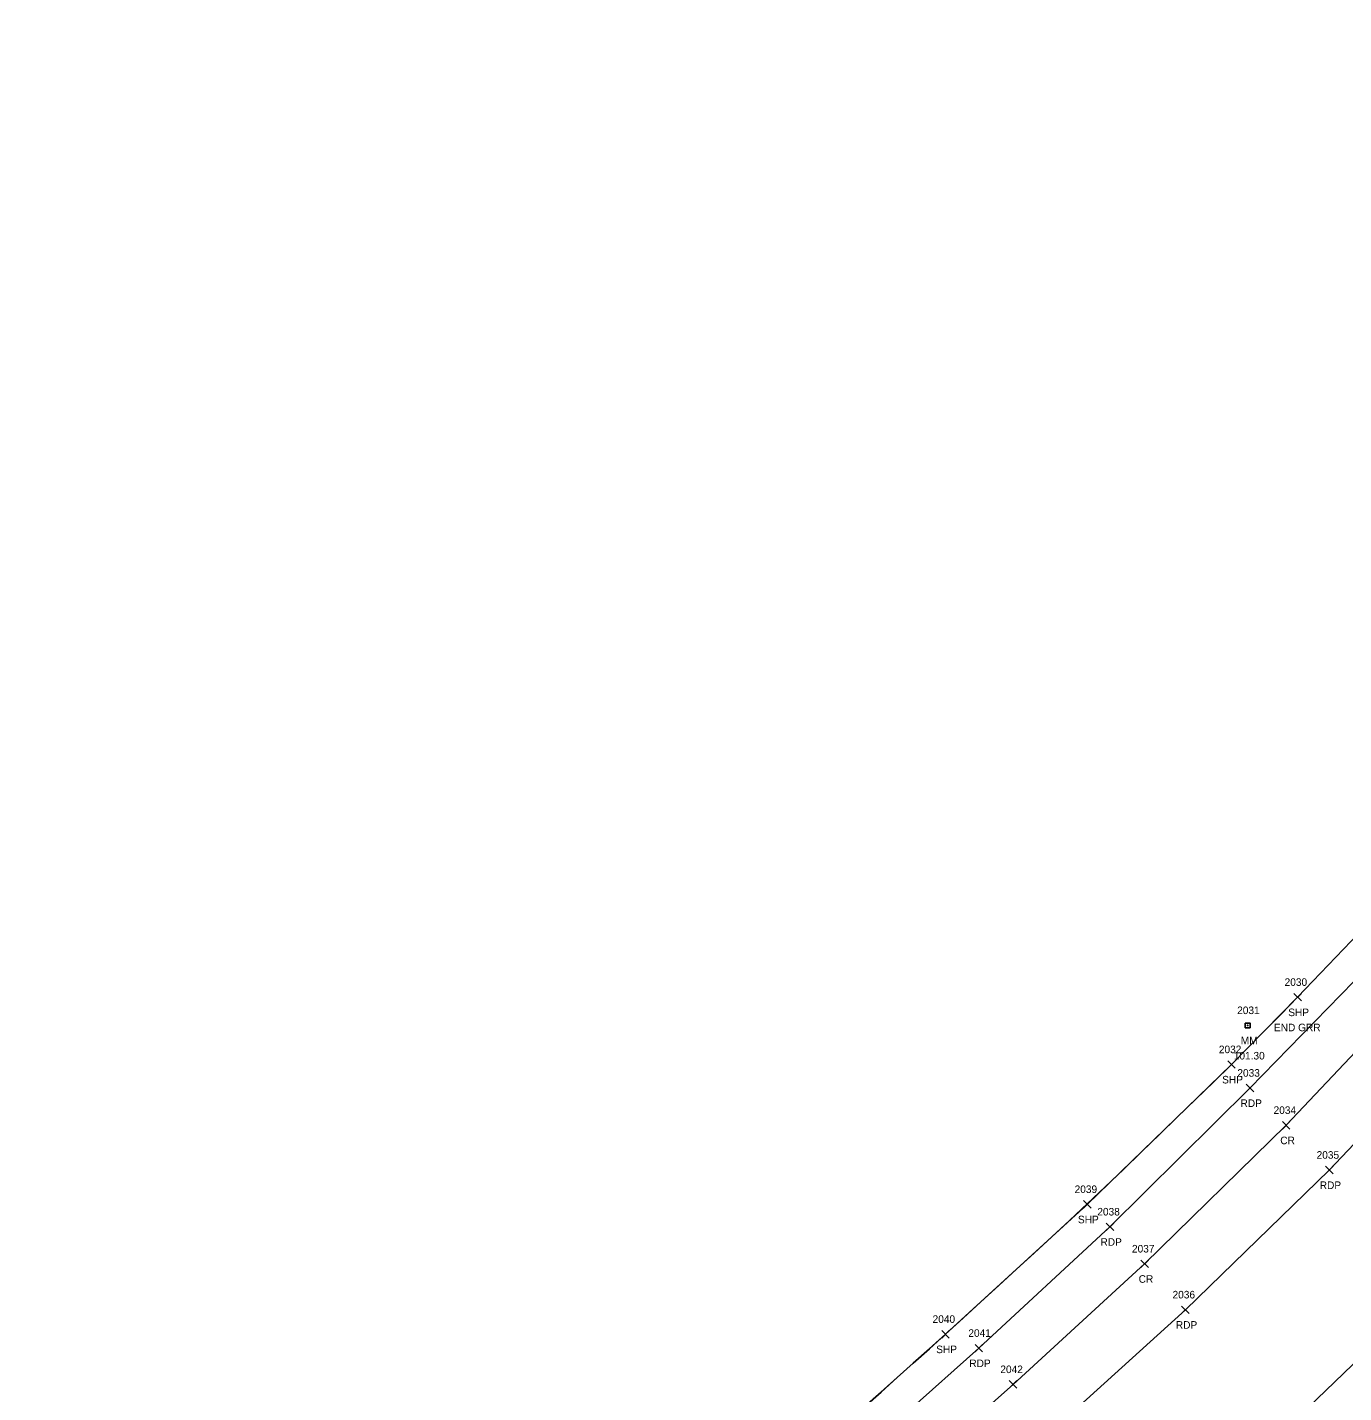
# Model space of a CAD drawing. Extents: x 1472022 to 1479249, y 777216 to 786527.
# Drawn here: x 1472693.8 to 1473041.7, y 778071.1 to 778431.9 of the extents above; entities that cross this region are included whole.
import ezdxf

# ---------------------------------------------------------------- set-up
doc = ezdxf.new("R2010")
doc.units = 0
for name, color, linetype in [('LSOGP', 7, 'Continuous'), ('P_A', 7, 'Continuous'), ('P_C', 7, 'Continuous'), ('P_I', 7, 'Continuous'), ('P_TIC', 7, 'Continuous'), ('PET', 7, 'Continuous'), ('PRC', 7, 'Continuous'), ('PSP', 7, 'Continuous'), ('S_A', 7, 'Continuous'), ('S_C', 7, 'Continuous'), ('S_I', 7, 'Continuous'), ('SRM', 7, 'Continuous')]:
    doc.layers.add(name, color=color, linetype=linetype)

msp = doc.modelspace()

# ---------------------------------------------------------------- linework, layer by layer
at = {"layer": 'LSOGP'}
msp.add_lwpolyline([(1473045.72, 778192.54), (1473041.66, 778188.31), (1473037.61, 778184.07), (1473033.55, 778179.83), (1473029.49, 778175.6), (1473025.13, 778171.15), (1473020.76, 778166.71), (1473016.39, 778162.26), (1473012.03, 778157.81), (1473007.26, 778153.19), (1473002.5, 778148.57), (1472997.74, 778143.95), (1472992.97, 778139.33), (1472988.21, 778134.71), (1472983.45, 778130.09), (1472978.68, 778125.47), (1472969.24, 778116.56), (1472964.55, 778112.27), (1472959.87, 778107.98), (1472955.19, 778103.69), (1472950.51, 778099.4), (1472945.83, 778095.11), (1472941.14, 778090.82), (1472936.46, 778086.53), (1472932.2, 778082.71), (1472927.94, 778078.9), (1472923.67, 778075.08), (1472919.41, 778071.26), (1472915.15, 778067.44)], dxfattribs=at)
at = {"layer": 'P_TIC'}
for points in [[(1473028.49, 778174.6), (1473030.49, 778176.6)], [(1473030.49, 778174.6), (1473028.49, 778176.6)], [(1473011.03, 778156.81), (1473013.03, 778158.81)], [(1473013.03, 778156.81), (1473011.03, 778158.81)], [(1473015.92, 778150.59), (1473017.92, 778152.59)], [(1473017.92, 778150.59), (1473015.92, 778152.59)], [(1473025.49, 778140.75), (1473027.49, 778142.75)], [(1473027.49, 778140.75), (1473025.49, 778142.75)], [(1473036.86, 778128.91), (1473038.86, 778130.91)], [(1473038.86, 778128.91), (1473036.86, 778130.91)], [(1472972.92, 778119.85), (1472974.92, 778121.85)], [(1472974.92, 778119.85), (1472972.92, 778121.85)], [(1472978.91, 778113.91), (1472980.91, 778115.91)], [(1472980.91, 778113.91), (1472978.91, 778115.91)], [(1472988.07, 778104.13), (1472990.07, 778106.13)], [(1472990.07, 778104.13), (1472988.07, 778106.13)], [(1472998.85, 778091.99), (1473000.85, 778093.99)], [(1473000.85, 778091.99), (1472998.85, 778093.99)], [(1472935.46, 778085.53), (1472937.46, 778087.53)], [(1472937.46, 778085.53), (1472935.46, 778087.53)], [(1472944.26, 778081.84), (1472946.26, 778083.84)], [(1472946.26, 778081.84), (1472944.26, 778083.84)], [(1472953.29, 778072.26), (1472955.29, 778074.26)], [(1472955.29, 778072.26), (1472953.29, 778074.26)]]:
    msp.add_lwpolyline(points, dxfattribs=at)
at = {"layer": 'PET'}
for points in [[(1473255.52, 778449.63), (1473221.14, 778399.57), (1473182.52, 778345.97), (1473145.62, 778298.63), (1473115.08, 778260.59), (1473080.6, 778220.31), (1473051.25, 778186.84), (1473016.92, 778151.59), (1472979.91, 778114.91), (1472945.26, 778082.84), (1472907.77, 778049.38), (1472868.55, 778015.69), (1472837.98, 777989.81), (1472804.85, 777962.23), (1472766.82, 777929.84), (1472722.68, 777892.48), (1472682.88, 777859.11)], [(1473280.39, 778434.36), (1473245.89, 778383.45), (1473206.13, 778328.04), (1473169.71, 778281.51), (1473137.09, 778240.78), (1473104.04, 778201.77), (1473072.67, 778166.5), (1473037.86, 778129.91), (1472999.85, 778092.99), (1472964.39, 778060.83), (1472926.51, 778026.82), (1472887.44, 777993.06), (1472857.66, 777967.76), (1472824.92, 777940.5), (1472785.25, 777907.17), (1472741.34, 777869.88), (1472700.25, 777835.4), (1472658.9, 777800.89)], [(1472684.83, 777767.44), (1472722.55, 777799.22), (1472766.23, 777836.23), (1472817.16, 777878.96), (1472857.89, 777913.52), (1472893.26, 777943.27), (1472939.5, 777982.83), (1472979.03, 778017.29), (1473015.7, 778051.25), (1473048.8, 778083.05), (1473084.2, 778118.03), (1473117.72, 778153.52), (1473150.86, 778190.79), (1473181.06, 778226.14), (1473213.03, 778266.55), (1473241.58, 778304.07), (1473271.79, 778346.69), (1473301.45, 778389.87), (1473329.64, 778433.49)]]:
    msp.add_lwpolyline(points, dxfattribs=at)
at = {"layer": 'PRC'}
msp.add_lwpolyline([(1473266.55, 778442.63), (1473232.46, 778392.44), (1473193.83, 778338.54), (1473156.79, 778291.23), (1473125.31, 778252.34), (1473091.58, 778212.42), (1473060.19, 778177.45), (1473026.49, 778141.75), (1472989.07, 778105.13), (1472954.29, 778073.26), (1472916.06, 778039.37), (1472877.51, 778005.85), (1472846.53, 777979.57), (1472813.91, 777952.49), (1472775.15, 777919.54), (1472731.22, 777882.43), (1472690.51, 777848.29)], dxfattribs=at)
at = {"layer": 'PSP'}
msp.add_lwpolyline([(1473248.4, 778453.47), (1473214.72, 778403.13), (1473176.48, 778350.2), (1473139.45, 778301.94), (1473109.83, 778265.56), (1473075.26, 778225.58), (1473045.72, 778192.54), (1473029.49, 778175.6), (1473012.03, 778157.81), (1472973.92, 778120.85), (1472936.46, 778086.53), (1472902.36, 778055.99), (1472863.3, 778022.57), (1472832.68, 777997.03), (1472798.65, 777968.31), (1472761.65, 777936.81), (1472716.04, 777898.78), (1472676.55, 777865.69)], dxfattribs=at)
at = {"layer": 'SRM'}
msp.add_lwpolyline([(1473015.68, 778168.77), (1473016.93, 778168.77), (1473016.93, 778167.52), (1473015.68, 778167.52)], close=True, dxfattribs=at)
msp.add_circle((1473016.31, 778168.14), 0.0833, dxfattribs=at)

# ---------------------------------------------------------------- texts
at = {"layer": 'P_A'}
for s, p in [('SHP', (1473027.03, 778170.6)), ('SHP', (1473009.56, 778152.81)), ('RDP', (1473014.41, 778146.59)), ('CR', (1473024.92, 778136.75)), ('RDP', (1473035.35, 778124.91)), ('SHP', (1472971.45, 778115.85)), ('RDP', (1472977.4, 778109.91)), ('CR', (1472987.5, 778100.13)), ('RDP', (1472997.33, 778087.99)), ('SHP', (1472934, 778081.53)), ('RDP', (1472942.75, 778077.84))]:
    msp.add_text(s, height=2, dxfattribs=at).set_placement(p)
at = {"layer": 'P_C'}
msp.add_text('END GRR', height=2, dxfattribs=at).set_placement((1473023.25, 778166.6))
at = {"layer": 'P_I'}
for s, p in [('2030', (1473026.07, 778178.6)), ('2032', (1473008.69, 778160.81)), ('2033', (1473013.58, 778154.59)), ('2034', (1473023.15, 778144.75)), ('2035', (1473034.52, 778132.91)), ('2039', (1472970.57, 778123.85)), ('2038', (1472976.57, 778117.91)), ('2037', (1472985.73, 778108.13)), ('2036', (1472996.45, 778095.99)), ('2040', (1472933.04, 778089.53)), ('2041', (1472942.49, 778085.84)), ('2042', (1472950.95, 778076.26))]:
    msp.add_text(s, height=2, dxfattribs=at).set_placement(p)
at = {"layer": 'S_A'}
msp.add_text('MM', height=2, dxfattribs=at).set_placement((1473014.49, 778163.14))
at = {"layer": 'S_C'}
msp.add_text('101.30', height=2, dxfattribs=at).set_placement((1473012.63, 778159.14))
at = {"layer": 'S_I'}
msp.add_text('2031', height=2, dxfattribs=at).set_placement((1473013.53, 778171.14))

doc.saveas('drawing.dxf')
